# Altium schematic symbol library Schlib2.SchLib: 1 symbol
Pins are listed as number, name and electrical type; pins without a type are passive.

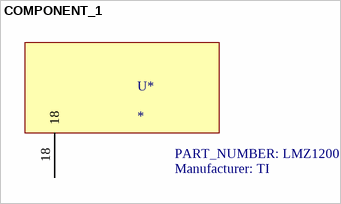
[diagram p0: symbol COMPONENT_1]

## COMPONENT_1
designator U*  PART_NUMBER: LMZ12003TZ-ADJ/NOPB  Manufacturer: TI
IC BUCK SYNC ADJ 3A TO-PMOD-7
footprint LMZ12003TZ_ADJ   (Footprint not found)
footprint Model Name (Footprint not found)
pins: 18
